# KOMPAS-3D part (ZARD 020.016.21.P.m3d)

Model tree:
1. Плоскость XY
2. Плоскость ZX
3. Плоскость ZY
4. Ось X
5. Ось Y
6. Ось Z
7. Начало координат
8. Булева операция:1
9. Булева операция:2
10. Булева операция:5
11. Булева операция:6
